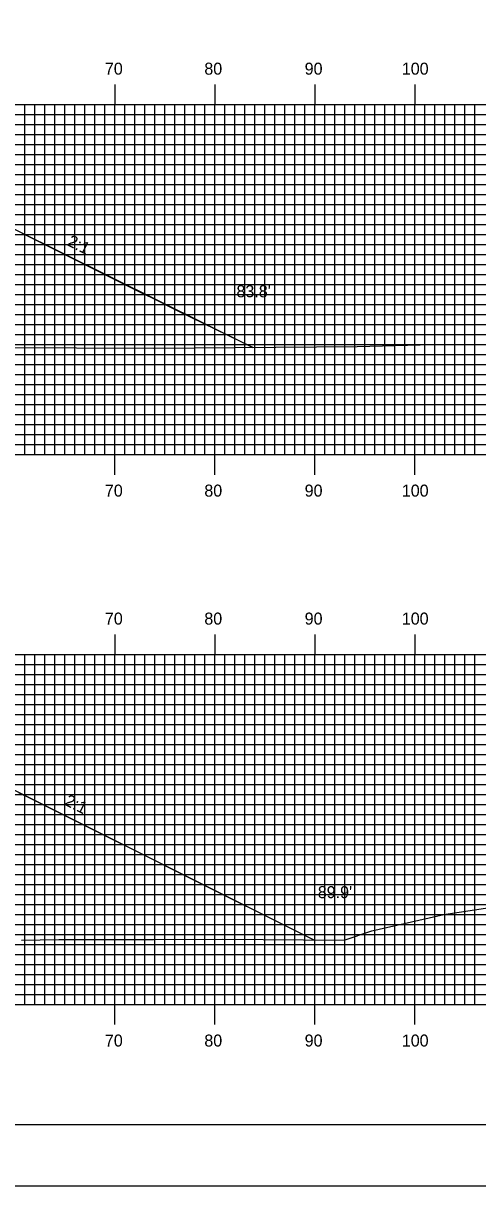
# Model space of a CAD drawing. Extents: x 1756675 to 1757019, y 442591 to 442811.
# Drawn here: x 1756901.9 to 1756947.4, y 442590.5 to 442706.8 of the extents above; entities that cross this region are included whole.
import ezdxf

# ---------------------------------------------------------------- set-up
doc = ezdxf.new("R2010")
doc.units = 0
for name, color, linetype in [('ANNOTATION', 7, 'Continuous'), ('BORDER', 7, 'Continuous'), ('D_Roadway_Centerline', 7, 'Continuous'), ('D_Roadway_SlopeLines', 7, 'Continuous'), ('D_Text_Standard', 7, 'Continuous'), ('H_V ANNOTATION', 7, 'Continuous'), ('MAJOR', 7, 'Continuous'), ('MINOR', 7, 'Continuous'), ('PLOT BOUNDARY', 7, 'Continuous'), ('S_Roadway_Centerline', 7, 'Continuous')]:
    doc.layers.add(name, color=color, linetype=linetype)

msp = doc.modelspace()

# ---------------------------------------------------------------- linework, layer by layer
at = {"layer": 'BORDER'}
msp.add_lwpolyline([(1756691.48, 442596.67), (1757011.48, 442596.67), (1757011.48, 442806.67), (1756691.48, 442806.67)], close=True, dxfattribs=at)
at = {"layer": 'D_Roadway_Centerline'}
for points in [[(1756901.83, 442685.8), (1756902.21, 442685.61), (1756902.21, 442685.61), (1756910.36, 442681.54), (1756911.69, 442680.88), (1756913.34, 442680.06), (1756913.88, 442679.79), (1756914.74, 442679.37), (1756917.38, 442678.05), (1756924.86, 442674.41), (1756924.86, 442674.41), (1756924.89, 442674.39)], [(1756901.46, 442629.89), (1756902.83, 442629.2), (1756909.21, 442626.01), (1756910.75, 442625.24), (1756912.98, 442624.13), (1756918.89, 442621.17), (1756922.13, 442619.55), (1756924.02, 442618.61), (1756924.5, 442618.37), (1756930.96, 442615.14)]]:
    msp.add_lwpolyline(points, dxfattribs=at)
at = {"layer": 'D_Roadway_SlopeLines'}
for points in [[(1756896.38, 442688.52), (1756924.89, 442674.39)], [(1756892.01, 442634.62), (1756930.96, 442615.14)]]:
    msp.add_lwpolyline(points, dxfattribs=at)
at = {"layer": 'MAJOR'}
for p, q in [((1756911.08, 442700.67), (1756911.08, 442698.67)), ((1756921.08, 442700.67), (1756921.08, 442698.67)), ((1756931.08, 442700.67), (1756931.08, 442698.67)), ((1756941.08, 442700.67), (1756941.08, 442698.67)), ((1756701.08, 442698.67), (1756981.08, 442698.67)), ((1756701.08, 442698.67), (1756981.08, 442698.67)), ((1756911.08, 442663.67), (1756911.08, 442698.67)), ((1756921.08, 442663.67), (1756921.08, 442698.67)), ((1756931.08, 442663.67), (1756931.08, 442698.67)), ((1756941.08, 442663.67), (1756941.08, 442698.67)), ((1756701.08, 442693.67), (1756981.08, 442693.67)), ((1756701.08, 442688.67), (1756981.08, 442688.67)), ((1756701.08, 442683.67), (1756981.08, 442683.67)), ((1756701.08, 442678.67), (1756981.08, 442678.67)), ((1756701.08, 442673.67), (1756981.08, 442673.67)), ((1756701.08, 442668.67), (1756981.08, 442668.67)), ((1756701.08, 442663.67), (1756981.08, 442663.67)), ((1756701.08, 442663.67), (1756981.08, 442663.67)), ((1756911.08, 442661.66), (1756911.08, 442663.67)), ((1756921.08, 442661.66), (1756921.08, 442663.67)), ((1756931.08, 442661.66), (1756931.08, 442663.67)), ((1756941.08, 442661.66), (1756941.08, 442663.67)), ((1756911.08, 442645.67), (1756911.08, 442643.67)), ((1756921.08, 442645.67), (1756921.08, 442643.67)), ((1756931.08, 442645.67), (1756931.08, 442643.67)), ((1756941.08, 442645.67), (1756941.08, 442643.67)), ((1756701.08, 442643.67), (1756981.08, 442643.67)), ((1756701.08, 442643.67), (1756981.08, 442643.67)), ((1756911.08, 442608.67), (1756911.08, 442643.67)), ((1756921.08, 442608.67), (1756921.08, 442643.67)), ((1756931.08, 442608.67), (1756931.08, 442643.67)), ((1756941.08, 442608.67), (1756941.08, 442643.67)), ((1756701.08, 442638.67), (1756981.08, 442638.67)), ((1756701.08, 442633.67), (1756981.08, 442633.67)), ((1756701.08, 442628.67), (1756981.08, 442628.67)), ((1756701.08, 442623.67), (1756981.08, 442623.67)), ((1756701.08, 442618.67), (1756981.08, 442618.67)), ((1756701.08, 442613.67), (1756981.08, 442613.67)), ((1756701.08, 442608.67), (1756981.08, 442608.67)), ((1756701.08, 442608.67), (1756981.08, 442608.67)), ((1756911.08, 442606.66), (1756911.08, 442608.67)), ((1756921.08, 442606.66), (1756921.08, 442608.67)), ((1756931.08, 442606.66), (1756931.08, 442608.67)), ((1756941.08, 442606.66), (1756941.08, 442608.67))]:
    msp.add_line(p, q, dxfattribs=at)
at = {"layer": 'MINOR'}
for p, q in [((1756902.08, 442663.67), (1756902.08, 442698.67)), ((1756903.08, 442663.67), (1756903.08, 442698.67)), ((1756904.08, 442663.67), (1756904.08, 442698.67)), ((1756905.08, 442663.67), (1756905.08, 442698.67)), ((1756906.08, 442663.67), (1756906.08, 442698.67)), ((1756907.08, 442663.67), (1756907.08, 442698.67)), ((1756908.08, 442663.67), (1756908.08, 442698.67)), ((1756909.08, 442663.67), (1756909.08, 442698.67)), ((1756910.08, 442663.67), (1756910.08, 442698.67)), ((1756912.08, 442663.67), (1756912.08, 442698.67)), ((1756913.08, 442663.67), (1756913.08, 442698.67)), ((1756914.08, 442663.67), (1756914.08, 442698.67)), ((1756915.08, 442663.67), (1756915.08, 442698.67)), ((1756916.08, 442663.67), (1756916.08, 442698.67)), ((1756917.08, 442663.67), (1756917.08, 442698.67)), ((1756918.08, 442663.67), (1756918.08, 442698.67)), ((1756919.08, 442663.67), (1756919.08, 442698.67)), ((1756920.08, 442663.67), (1756920.08, 442698.67)), ((1756922.08, 442663.67), (1756922.08, 442698.67)), ((1756923.08, 442663.67), (1756923.08, 442698.67)), ((1756924.08, 442663.67), (1756924.08, 442698.67)), ((1756925.08, 442663.67), (1756925.08, 442698.67)), ((1756926.08, 442663.67), (1756926.08, 442698.67)), ((1756927.08, 442663.67), (1756927.08, 442698.67)), ((1756928.08, 442663.67), (1756928.08, 442698.67)), ((1756929.08, 442663.67), (1756929.08, 442698.67)), ((1756930.08, 442663.67), (1756930.08, 442698.67)), ((1756932.08, 442663.67), (1756932.08, 442698.67)), ((1756933.08, 442663.67), (1756933.08, 442698.67)), ((1756934.08, 442663.67), (1756934.08, 442698.67)), ((1756935.08, 442663.67), (1756935.08, 442698.67)), ((1756936.08, 442663.67), (1756936.08, 442698.67)), ((1756937.08, 442663.67), (1756937.08, 442698.67)), ((1756938.08, 442663.67), (1756938.08, 442698.67)), ((1756939.08, 442663.67), (1756939.08, 442698.67)), ((1756940.08, 442663.67), (1756940.08, 442698.67)), ((1756942.08, 442663.67), (1756942.08, 442698.67)), ((1756943.08, 442663.67), (1756943.08, 442698.67)), ((1756944.08, 442663.67), (1756944.08, 442698.67)), ((1756945.08, 442663.67), (1756945.08, 442698.67)), ((1756946.08, 442663.67), (1756946.08, 442698.67)), ((1756947.08, 442663.67), (1756947.08, 442698.67)), ((1756701.08, 442697.67), (1756981.08, 442697.67)), ((1756701.08, 442696.67), (1756981.08, 442696.67)), ((1756701.08, 442695.67), (1756981.08, 442695.67)), ((1756701.08, 442694.67), (1756981.08, 442694.67)), ((1756701.08, 442692.67), (1756981.08, 442692.67)), ((1756701.08, 442691.67), (1756981.08, 442691.67)), ((1756701.08, 442690.67), (1756981.08, 442690.67)), ((1756701.08, 442689.67), (1756981.08, 442689.67)), ((1756701.08, 442687.67), (1756981.08, 442687.67)), ((1756701.08, 442686.67), (1756981.08, 442686.67)), ((1756701.08, 442685.67), (1756981.08, 442685.67)), ((1756701.08, 442684.67), (1756981.08, 442684.67)), ((1756701.08, 442682.67), (1756981.08, 442682.67)), ((1756701.08, 442681.67), (1756981.08, 442681.67)), ((1756701.08, 442680.67), (1756981.08, 442680.67)), ((1756701.08, 442679.67), (1756981.08, 442679.67)), ((1756701.08, 442677.67), (1756981.08, 442677.67)), ((1756701.08, 442676.67), (1756981.08, 442676.67)), ((1756701.08, 442675.67), (1756981.08, 442675.67)), ((1756701.08, 442674.67), (1756981.08, 442674.67)), ((1756701.08, 442672.67), (1756981.08, 442672.67)), ((1756701.08, 442671.67), (1756981.08, 442671.67)), ((1756701.08, 442670.67), (1756981.08, 442670.67)), ((1756701.08, 442669.67), (1756981.08, 442669.67)), ((1756701.08, 442667.67), (1756981.08, 442667.67)), ((1756701.08, 442666.67), (1756981.08, 442666.67)), ((1756701.08, 442665.67), (1756981.08, 442665.67)), ((1756701.08, 442664.67), (1756981.08, 442664.67)), ((1756902.08, 442608.67), (1756902.08, 442643.67)), ((1756903.08, 442608.67), (1756903.08, 442643.67)), ((1756904.08, 442608.67), (1756904.08, 442643.67)), ((1756905.08, 442608.67), (1756905.08, 442643.67)), ((1756906.08, 442608.67), (1756906.08, 442643.67)), ((1756907.08, 442608.67), (1756907.08, 442643.67)), ((1756908.08, 442608.67), (1756908.08, 442643.67)), ((1756909.08, 442608.67), (1756909.08, 442643.67)), ((1756910.08, 442608.67), (1756910.08, 442643.67)), ((1756912.08, 442608.67), (1756912.08, 442643.67)), ((1756913.08, 442608.67), (1756913.08, 442643.67)), ((1756914.08, 442608.67), (1756914.08, 442643.67)), ((1756915.08, 442608.67), (1756915.08, 442643.67)), ((1756916.08, 442608.67), (1756916.08, 442643.67)), ((1756917.08, 442608.67), (1756917.08, 442643.67)), ((1756918.08, 442608.67), (1756918.08, 442643.67)), ((1756919.08, 442608.67), (1756919.08, 442643.67)), ((1756920.08, 442608.67), (1756920.08, 442643.67)), ((1756922.08, 442608.67), (1756922.08, 442643.67)), ((1756923.08, 442608.67), (1756923.08, 442643.67)), ((1756924.08, 442608.67), (1756924.08, 442643.67)), ((1756925.08, 442608.67), (1756925.08, 442643.67)), ((1756926.08, 442608.67), (1756926.08, 442643.67)), ((1756927.08, 442608.67), (1756927.08, 442643.67)), ((1756928.08, 442608.67), (1756928.08, 442643.67)), ((1756929.08, 442608.67), (1756929.08, 442643.67)), ((1756930.08, 442608.67), (1756930.08, 442643.67)), ((1756932.08, 442608.67), (1756932.08, 442643.67)), ((1756933.08, 442608.67), (1756933.08, 442643.67)), ((1756934.08, 442608.67), (1756934.08, 442643.67)), ((1756935.08, 442608.67), (1756935.08, 442643.67)), ((1756936.08, 442608.67), (1756936.08, 442643.67)), ((1756937.08, 442608.67), (1756937.08, 442643.67)), ((1756938.08, 442608.67), (1756938.08, 442643.67)), ((1756939.08, 442608.67), (1756939.08, 442643.67)), ((1756940.08, 442608.67), (1756940.08, 442643.67)), ((1756942.08, 442608.67), (1756942.08, 442643.67)), ((1756943.08, 442608.67), (1756943.08, 442643.67)), ((1756944.08, 442608.67), (1756944.08, 442643.67)), ((1756945.08, 442608.67), (1756945.08, 442643.67)), ((1756946.08, 442608.67), (1756946.08, 442643.67)), ((1756947.08, 442608.67), (1756947.08, 442643.67)), ((1756701.08, 442642.67), (1756981.08, 442642.67)), ((1756701.08, 442641.67), (1756981.08, 442641.67)), ((1756701.08, 442640.67), (1756981.08, 442640.67)), ((1756701.08, 442639.67), (1756981.08, 442639.67)), ((1756701.08, 442637.67), (1756981.08, 442637.67)), ((1756701.08, 442636.67), (1756981.08, 442636.67)), ((1756701.08, 442635.67), (1756981.08, 442635.67)), ((1756701.08, 442634.67), (1756981.08, 442634.67)), ((1756701.08, 442632.67), (1756981.08, 442632.67)), ((1756701.08, 442631.67), (1756981.08, 442631.67)), ((1756701.08, 442630.67), (1756981.08, 442630.67)), ((1756701.08, 442629.67), (1756981.08, 442629.67)), ((1756701.08, 442627.67), (1756981.08, 442627.67)), ((1756701.08, 442626.67), (1756981.08, 442626.67)), ((1756701.08, 442625.67), (1756981.08, 442625.67)), ((1756701.08, 442624.67), (1756981.08, 442624.67)), ((1756701.08, 442622.67), (1756981.08, 442622.67)), ((1756701.08, 442621.67), (1756981.08, 442621.67)), ((1756701.08, 442620.67), (1756981.08, 442620.67)), ((1756701.08, 442619.67), (1756981.08, 442619.67)), ((1756701.08, 442617.67), (1756981.08, 442617.67)), ((1756701.08, 442616.67), (1756981.08, 442616.67)), ((1756701.08, 442615.67), (1756981.08, 442615.67)), ((1756701.08, 442614.67), (1756981.08, 442614.67)), ((1756701.08, 442612.67), (1756981.08, 442612.67)), ((1756701.08, 442611.67), (1756981.08, 442611.67)), ((1756701.08, 442610.67), (1756981.08, 442610.67)), ((1756701.08, 442609.67), (1756981.08, 442609.67))]:
    msp.add_line(p, q, dxfattribs=at)
at = {"layer": 'PLOT BOUNDARY'}
msp.add_lwpolyline([(1756675.3, 442590.55), (1757015.3, 442590.55), (1757015.3, 442810.55), (1756675.3, 442810.55)], close=True, dxfattribs=at)
at = {"layer": 'S_Roadway_Centerline'}
for points in [[(1756701.08, 442674.81), (1756701.68, 442674.81), (1756706.12, 442674.79), (1756709.1, 442674.81), (1756750.01, 442674.91), (1756753.92, 442674.86), (1756780.55, 442674.65), (1756793.34, 442674.46), (1756796.09, 442674.27), (1756805.61, 442673.9), (1756808.09, 442673.88), (1756821.91, 442673.54), (1756842.06, 442673.4), (1756851.64, 442673.44), (1756857.38, 442673.52), (1756881.46, 442674.48), (1756884.01, 442674.46), (1756914.99, 442674.3), (1756935.3, 442674.49), (1756942.87, 442674.67), (1756956.22, 442674.7), (1756981.08, 442675.14)], [(1756901.77, 442615.11), (1756905.48, 442615.16), (1756914.95, 442615.16), (1756921.83, 442615.2), (1756934, 442615.12), (1756936.78, 442616.05), (1756943.97, 442617.66), (1756948.57, 442618.38), (1756949.6, 442618.72), (1756949.73, 442618.73), (1756957.97, 442619.01), (1756972.56, 442619.51), (1756978.49, 442619.7), (1756980.41, 442619.67), (1756981.08, 442619.66)]]:
    msp.add_lwpolyline(points, dxfattribs=at)

# ---------------------------------------------------------------- texts
at = {"layer": 'ANNOTATION'}
for rotation, p in [(333.4437, (1756906.22, 442684.64)), (333.4278, (1756905.96, 442628.68))]:
    msp.add_text('2:1', height=1.2, rotation=rotation, dxfattribs=at).set_placement(p)
at = {"layer": 'D_Text_Standard'}
for s, p in [("83.8'", (1756923.24, 442679.41)), ("89.9'", (1756931.37, 442619.31))]:
    msp.add_text(s, height=1.2, dxfattribs=at).set_placement(p)
at = {"layer": 'H_V ANNOTATION'}
for s, p in [('70', (1756910.09, 442701.67)), ('80', (1756920.03, 442701.67)), ('90', (1756930.06, 442701.67)), ('100', (1756939.77, 442701.67)), ('70', (1756910.09, 442659.47)), ('80', (1756920.03, 442659.47)), ('90', (1756930.06, 442659.47)), ('100', (1756939.77, 442659.47)), ('70', (1756910.09, 442646.67)), ('80', (1756920.03, 442646.67)), ('90', (1756930.06, 442646.67)), ('100', (1756939.77, 442646.67)), ('70', (1756910.09, 442604.47)), ('80', (1756920.03, 442604.47)), ('90', (1756930.06, 442604.47)), ('100', (1756939.77, 442604.47))]:
    msp.add_text(s, height=1.2, dxfattribs=at).set_placement(p)

doc.saveas('drawing.dxf')
